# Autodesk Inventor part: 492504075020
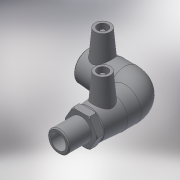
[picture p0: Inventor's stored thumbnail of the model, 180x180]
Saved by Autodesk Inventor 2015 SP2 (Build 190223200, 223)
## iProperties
Created: 2017-06
Part Number: 492504075020
Material: Generic
Description: PLASSON 90° ELBOW MALE TRANSITION 75-2"
Document SubType Name: Modeling
Designer: KIM
Mass: 827.797 g
Surface Area: 1357.15 cm^2
Volume: 827.797 cm^3
Density: 1 g/cm^3
Appearance: Default
Author: KIM
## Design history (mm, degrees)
derived "492504.ipt"
feature "Solid1::492504.ipt"
tag "TaggingFeature1"
body "Solid1"
other parameters: "d2" = 98, "d4" = 52.66667, "d5" = 88.2, "d8" = 168 deg, "d10" = 27.6, "d11" = 9.2, "d29" = 62, "d30" = 15, "d31" = 86.9, "d34" = 5 deg, "d41" = 4, "d42" = 14, "d43" = 0, "d48" = 109, "d49" = 75, "d50" = 63.75, "d51" = 27.6, "d52" = 69, "d54" = 90 deg, "d57" = 75, "d58" = 69, "d59" = 0, "d61" = 90 deg, "d86" = 3, "d87" = 0, "d93" = 0.1, "d94" = 10.25, "d95" = 59.614, "d96" = 41.7298, "d97" = 59, "d98" = 41, "d99" = 98, "d100" = 36.9, "d102" = 3, "d106" = 0, "d_" = 75, "L_" = 199, "L_1" = 69, "D_" = 59, "A_" = 62, "d_2" = 12, "L_2" = 41, "D_1" = 98, "R_" = 59.614
